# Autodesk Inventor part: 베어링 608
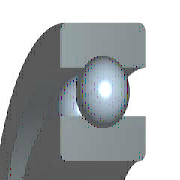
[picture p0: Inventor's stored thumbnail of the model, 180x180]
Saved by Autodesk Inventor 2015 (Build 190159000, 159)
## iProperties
IsCustomPart: 1
Created: 2012-02
Part Number: 베어링 608
Material: 강철, 연강
Description: 깊은 그루브 볼 베어링
Document SubType Name: Modeling
Standard: KS B 2023
Designer: mduedu
Standards Organization: KS
Language: ko-KR
Size Designation: 608 - 8 x 22 x 7
Categories: <MemberInstance><Categories><Category DisplayName="샤프트 부품" InternalName="7f7aeb1f-a693-4053-b835-cee3144e0d98" Mnemonic="SHFT"><Category DisplayName="베어링" Inter
Density: 7.85 g/cm^3
Appearance: 노란색
Mass: 12.145 g
Surface Area: 20.0754 cm^2
Volume: 1.54714 cm^3
Author: mduedu
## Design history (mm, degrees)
sketch "스케치" dims "d0" = 3.64 (= -0.26 x WD + 0.26 x BD)
  geometry: L1 (1.68, 7.5)-(5.32, 7.5); L2 (3.5, 7.5)-(3.5, 5.68); L3 (3.5, 7.5)-(3.5, 9.32); L4 (2.148, 6.282)-(0, 6.282); L5 (0, 4)-(7, 4); L6 (2.148, 8.718)-(0, 8.718); L7 (0, 11)-(7, 11); L8 (7, 4)-(7, 6.282); L9 (4.852, 6.282)-(7, 6.282); L10 (4.852, 8.718)-(7, 8.718); L11 (7, 11)-(7, 8.718); L12 (-1.4, 0)-(8.4, 0) reference; L13 (0, -0.3)-(0, 5.3) reference
  constraints: 22 end point, 4 point on line, 2 collinear, 2 perpendicular, 2 symmetric about line, 1 midpoint, 1 parallel, 14 other
  dimensions: "d9" = 8 diameter of L5 L12 (= WD); "d11" = 22 diameter of L7 L12 (= BD); "d12" = 7 distance between parallel lines of L8 L13 (= KB); "d13" = 12.564 diameter of L9 L12 (= 0.326 x BD + 0.674 x WD)
revolve "본체" stored, may be unused: angle "d6" = 90 deg
revolve "볼" stored, may be unused: angle "d7" = 90 deg
pattern_circular "IDS_ARRAYBALL[SIMPL:T]" dims angle "d3" = 360 deg
body "Solid1"
fillet "모깎기1" dims "d1" = 0.3 (= KRS)
other parameters: "WD" = 8 [user parameter; used in 5 equation terms], "BD" = 22 [user parameter; used in 5 equation terms], "KB" = 7 [user parameter; used in 1 equation term], "KRS" = 0.3 [user parameter; used in 1 equation term], "d4" = 0, "d5" = 0, "d8" = 0, "d14" = 0, "d15" = 0, "BBA" = 0 [user parameter], "BC0" = 1370000 [user parameter], "BC" = 3250000 [user parameter], "BR" = 11 (= 0.5 x BD) [user parameter], "WR" = 4 (= 0.5 x WD) [user parameter]
